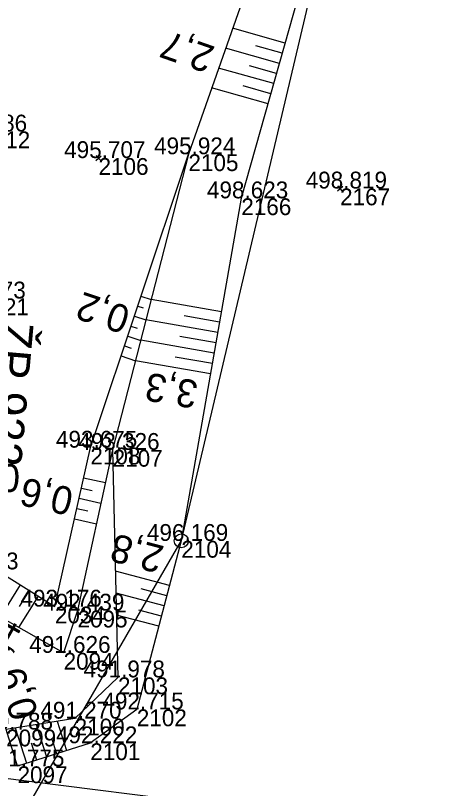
# Model space of a CAD drawing. Extents: x -1234191 to 23050, y -1290331 to -741191.
# Drawn here: x -864634.6 to -864603.9, y -1102729.2 to -1102674 of the extents above; entities that cross this region are included whole.
import ezdxf

# ---------------------------------------------------------------- set-up
doc = ezdxf.new("R2010")
doc.units = 0
for name, color, linetype in [('Vrstva 48', 7, 'Continuous'), ('Vrstva 49', 7, 'Continuous'), ('Vrstva 5', 7, 'Continuous'), ('Vrstva 53', 7, 'Continuous'), ('Vrstva 55', 7, 'Continuous'), ('Vrstva 60', 7, 'Continuous'), ('Vrstva 61', 7, 'Continuous'), ('Vrstva 63', 7, 'Continuous')]:
    doc.layers.add(name, color=color, linetype=linetype)

msp = doc.modelspace()

# ---------------------------------------------------------------- linework, layer by layer
at = {"layer": 'Vrstva 48'}
for p, q in [((-864615.367, -1102676.015), (-864619.119, -1102674.955)), ((-864615.774, -1102677.458), (-864619.616, -1102676.373)), ((-864615.57, -1102676.736), (-864617.469, -1102676.2)), ((-864616.182, -1102678.902), (-864620.113, -1102677.792)), ((-864615.978, -1102678.18), (-864617.921, -1102677.631)), ((-864616.589, -1102680.345), (-864620.61, -1102679.21)), ((-864616.386, -1102679.623), (-864618.373, -1102679.062)), ((-864625.653, -1102694.075), (-864624.927, -1102694.318)), ((-864619.912, -1102695.188), (-864624.925, -1102694.311)), ((-864625.89, -1102694.787), (-864625.502, -1102694.917)), ((-864626.128, -1102695.498), (-864625.3, -1102695.775)), ((-864620.17, -1102696.666), (-864625.298, -1102695.768)), ((-864620.041, -1102695.927), (-864622.576, -1102695.483)), ((-864626.366, -1102696.209), (-864625.926, -1102696.356)), ((-864626.603, -1102696.921), (-864625.673, -1102697.232)), ((-864620.429, -1102698.143), (-864625.672, -1102697.225)), ((-864620.3, -1102697.405), (-864622.892, -1102696.951)), ((-864626.841, -1102697.632), (-864626.35, -1102697.796)), ((-864627.079, -1102698.344), (-864626.047, -1102698.688)), ((-864620.558, -1102698.882), (-864623.208, -1102698.418)), ((-864620.688, -1102699.621), (-864626.045, -1102698.683)), ((-864629.745, -1102707.037), (-864628.187, -1102707.385)), ((-864629.908, -1102707.769), (-864629.127, -1102707.943)), ((-864630.071, -1102708.501), (-864628.507, -1102708.85)), ((-864630.235, -1102709.233), (-864629.451, -1102709.408)), ((-864630.398, -1102709.965), (-864628.827, -1102710.316)), ((-864623.617, -1102714.733), (-864627.472, -1102713.716)), ((-864634.265, -1102714.687), (-864635.698, -1102716.977)), ((-864633.629, -1102715.084), (-864634.337, -1102716.216)), ((-864623.808, -1102715.458), (-864625.631, -1102714.977)), ((-864632.994, -1102715.482), (-864634.391, -1102717.716)), ((-864624, -1102716.184), (-864627.435, -1102715.277)), ((-864624.191, -1102716.909), (-864625.804, -1102716.483)), ((-864624.383, -1102717.634), (-864627.399, -1102716.838)), ((-864630.943, -1102726.519), (-864631.607, -1102724.426)), ((-864633.802, -1102727.427), (-864634.603, -1102724.904)), ((-864632.373, -1102726.973), (-864633.105, -1102724.665)), ((-864633.087, -1102727.2), (-864633.471, -1102725.992)), ((-864631.658, -1102726.746), (-864632.007, -1102725.646))]:
    msp.add_line(p, q, dxfattribs=at)
at = {"layer": 'Vrstva 49'}
for p, q in [((-864628.868, -1102684.385), (-864628.498, -1102684.049)), ((-864628.515, -1102684.402), (-864628.851, -1102684.032)), ((-864611.63, -1102686.556), (-864611.26, -1102686.22)), ((-864611.277, -1102686.573), (-864611.613, -1102686.203))]:
    msp.add_line(p, q, dxfattribs=at)
for points in [[(-864613.106, -1102519.534), (-864608.731, -1102535.344), (-864610.609, -1102556.214), (-864608.338, -1102568.764), (-864606.542, -1102583.213), (-864604.718, -1102600.772), (-864603.921, -1102618.075), (-864604.786, -1102634.966), (-864612.713, -1102666.617), (-864618.494, -1102687.09), (-864622.775, -1102711.543), (-864625.95, -1102723.573), (-864629.27, -1102725.988), (-864634.461, -1102727.636), (-864635.275, -1102725.011)], [(-864617.004, -1102519.74), (-864614.172, -1102532.434), (-864615.402, -1102546.037), (-864618.648, -1102562.646), (-864611.16, -1102570.323), (-864610.132, -1102583.267), (-864608.138, -1102601.898), (-864609.196, -1102618.623), (-864609.582, -1102636.926), (-864613.842, -1102655.868), (-864618.302, -1102672.622), (-864622.268, -1102683.945), (-864627.676, -1102705.046), (-864627.294, -1102721.286), (-864630.384, -1102724.231), (-864635.275, -1102725.011)], [(-864627.676, -1102705.046), (-864630.183, -1102716.52), (-864631.174, -1102719.535), (-864638.752, -1102715.251), (-864639.483, -1102710.021), (-864638.88, -1102694.349), (-864638.117, -1102682.338), (-864637.82, -1102665.455), (-864639.031, -1102633.454), (-864639.918, -1102617.134), (-864639.253, -1102592.265), (-864636.142, -1102586.379), (-864633.035, -1102578.956), (-864627.386, -1102571.169), (-864624.706, -1102565.816), (-864619.99, -1102564.059), (-864618.648, -1102562.646)], [(-864611.16, -1102570.323), (-864617.834, -1102579.783), (-864626.546, -1102581.842), (-864634.835, -1102588.338), (-864637.585, -1102593.088), (-864638.093, -1102601.894), (-864637.883, -1102608.98), (-864639.205, -1102618.186), (-864637.886, -1102622.617), (-864637.628, -1102630.461), (-864637.173, -1102646.572), (-864636.24, -1102660.531), (-864636.257, -1102663.054), (-864637.245, -1102666.193), (-864637.127, -1102682.32), (-864637.223, -1102694.239), (-864637.961, -1102712.375), (-864631.796, -1102716.231)], [(-864631.796, -1102716.231), (-864629.265, -1102704.888), (-864622.268, -1102683.945)]]:
    msp.add_lwpolyline(points, dxfattribs=at)
at = {"layer": 'Vrstva 5'}
msp.add_line((-864608.126, -1102731.919), (-864642.493, -1102727.608), dxfattribs=at)
at = {"layer": 'Vrstva 53'}
msp.add_line((-864622.779, -1102711.593), (-864622.771, -1102711.493), dxfattribs=at)
msp.add_lwpolyline([(-864685.34, -1102369.7), (-864652.19, -1102431.45), (-864651.08, -1102433.92), (-864649.81, -1102436.72), (-864644.67, -1102440.9), (-864637.86, -1102447.68), (-864634.66, -1102450.05), (-864628.74, -1102455.44), (-864614.16, -1102466.94), (-864608.82, -1102469.48), (-864608.15, -1102493.66), (-864617.6, -1102495.16), (-864625.8, -1102502.03), (-864631.68, -1102514.84), (-864618.76, -1102517.37), (-864614.67, -1102518.17), (-864613.23, -1102518.45), (-864607.97, -1102568.96), (-864604.71, -1102634.96), (-864611.4, -1102663.26), (-864622.78, -1102711.51), (-864635.49, -1102733.5), (-864648.81, -1102800.46)], dxfattribs=at)
msp.add_circle((-864622.775, -1102711.543), 0.499, dxfattribs=at)
at = {"layer": 'Vrstva 55'}
msp.add_lwpolyline([(-864685.34, -1102369.7), (-864652.19, -1102431.45), (-864635.26, -1102468.98), (-864625.8, -1102502.03), (-864631.68, -1102514.84), (-864613.23, -1102518.45), (-864607.97, -1102568.96), (-864611.13, -1102641.68), (-864611.4, -1102663.26), (-864622.78, -1102711.51), (-864635.49, -1102733.5), (-864648.81, -1102800.46), (-864676.09, -1102867.88), (-864677.03, -1102870.08)], dxfattribs=at)
at = {"layer": 'Vrstva 60'}
for p, q in [((-864622.268, -1102683.945), (-864622.268, -1102683.945)), ((-864628.683, -1102684.217), (-864628.683, -1102684.217)), ((-864611.445, -1102686.388), (-864611.445, -1102686.388)), ((-864618.494, -1102687.09), (-864618.494, -1102687.09)), ((-864629.265, -1102704.888), (-864629.265, -1102704.888)), ((-864627.676, -1102705.046), (-864627.676, -1102705.046)), ((-864622.775, -1102711.543), (-864622.775, -1102711.543)), ((-864631.796, -1102716.231), (-864631.796, -1102716.231)), ((-864630.183, -1102716.52), (-864630.183, -1102716.52)), ((-864631.174, -1102719.535), (-864631.174, -1102719.535)), ((-864627.294, -1102721.286), (-864627.294, -1102721.286)), ((-864625.95, -1102723.573), (-864625.95, -1102723.573)), ((-864630.384, -1102724.231), (-864630.384, -1102724.231)), ((-864629.27, -1102725.988), (-864629.27, -1102725.988)), ((-864634.461, -1102727.636), (-864634.461, -1102727.636))]:
    msp.add_line(p, q, dxfattribs=at)

# ---------------------------------------------------------------- texts
at = {"layer": 'Vrstva 48'}
for s, rotation, p in [('2,7', 160.6967, (-864620.281, -1102676.304)), ('0,2', 161.5257, (-864626.292, -1102694.908)), ('3,3', 170.0698, (-864621.481, -1102700.156)), ('0,5', 177.7966, (-864634.249, -1102706.083)), ('0,6', 167.4215, (-864630.363, -1102707.811)), ('2,8', 165.2154, (-864623.905, -1102711.951)), ('1,4', 60.5196, (-864635.914, -1102720.899)), ('0,9', 107.6132, (-864632.953, -1102723.924))]:
    msp.add_text(s, height=2, rotation=rotation, dxfattribs=at).set_placement(p)
at = {"layer": 'Vrstva 60'}
for s, p in [('2012', (-864637.127, -1102683.52)), ('2105', (-864622.268, -1102685.145)), ('2106', (-864628.683, -1102685.417)), ('2167', (-864611.445, -1102687.588)), ('2166', (-864618.494, -1102688.29)), ('2021', (-864637.223, -1102695.439)), ('2108', (-864629.265, -1102706.088)), ('2107', (-864627.676, -1102706.246)), ('2104', (-864622.775, -1102712.743)), ('2033', (-864637.961, -1102713.575)), ('2034', (-864631.796, -1102717.431)), ('2095', (-864630.183, -1102717.72)), ('2094', (-864631.174, -1102720.735)), ('2103', (-864627.294, -1102722.486)), ('2102', (-864625.95, -1102724.773)), ('2100', (-864630.384, -1102725.431)), ('2099', (-864635.275, -1102726.211)), ('2101', (-864629.27, -1102727.188)), ('2097', (-864634.461, -1102728.836))]:
    msp.add_text(s, height=1.2, dxfattribs=at).set_placement(p)
at = {"layer": 'Vrstva 61'}
for s, p in [('494.586', (-864639.579, -1102682.32)), ('495.707', (-864631.135, -1102684.217)), ('495.924', (-864624.719, -1102683.945)), ('498.819', (-864613.899, -1102686.388)), ('498.623', (-864620.946, -1102687.09)), ('494.173', (-864639.675, -1102694.239)), ('493.675', (-864631.721, -1102704.888)), ('493.326', (-864630.128, -1102705.046)), ('496.169', (-864625.229, -1102711.543)), ('493.176', (-864634.248, -1102716.231)), ('492.439', (-864632.637, -1102716.52)), ('491.626', (-864633.626, -1102719.535)), ('491.978', (-864629.748, -1102721.286)), ('492.715', (-864628.406, -1102723.573)), ('491.270', (-864632.835, -1102724.231)), ('490.788', (-864637.729, -1102725.011)), ('492.222', (-864631.718, -1102725.988)), ('491.775', (-864636.917, -1102727.636))]:
    msp.add_text(s, height=1.2, dxfattribs=at).set_placement(p)
at = {"layer": 'Vrstva 63'}
msp.add_text('ŽP 922', height=2.4, rotation=264.9349, dxfattribs=at).set_placement((-864635.696, -1102695.785))

doc.saveas('drawing.dxf')
